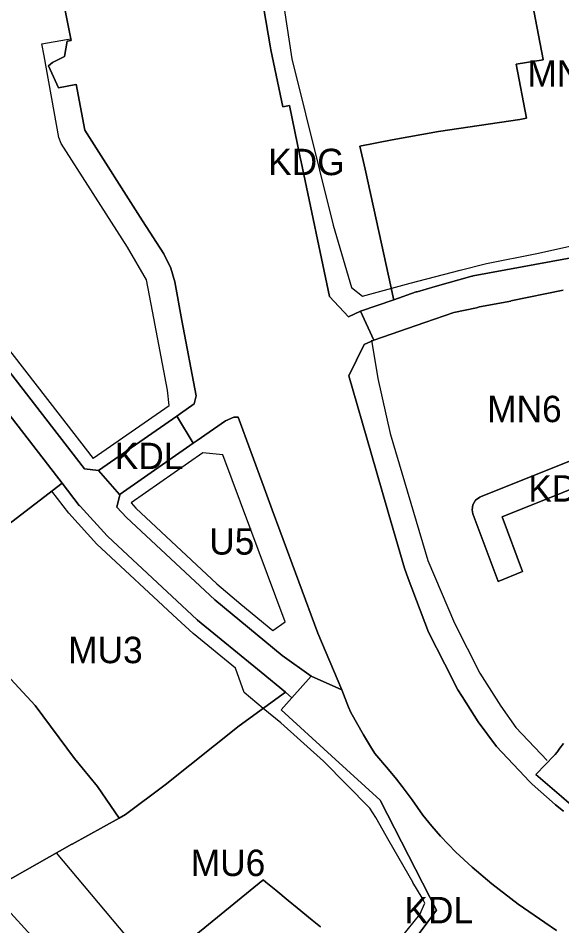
# Model space of a CAD drawing. Extents: x 7425930 to 7427318, y 5544765 to 5546387.
# Drawn here: x 7426439.3 to 7426645.2, y 5545452.3 to 5545796 of the extents above; entities that cross this region are included whole.
import ezdxf

# ---------------------------------------------------------------- set-up
doc = ezdxf.new("R2010")
doc.units = 0
for name, color, linetype in [('linie_rozgraniczajace', 7, 'Continuous'), ('linie_zabudowy_nieprzekraczalne', 7, 'Continuous'), ('linie_zabudowy_obowiazujace', 7, 'Continuous'), ('oznaczenia_przeznaczen', 7, 'Continuous')]:
    doc.layers.add(name, color=color, linetype=linetype)

msp = doc.modelspace()

# ---------------------------------------------------------------- linework, layer by layer
at = {"layer": 'linie_rozgraniczajace'}
for points in [[(7426447.87, 5545845.05), (7426459.42, 5545787.56), (7426457.84, 5545787.26), (7426456.9, 5545781.47), (7426452.3, 5545779.26), (7426450.8, 5545778.01), (7426454.62, 5545769.7), (7426461.08, 5545770.97), (7426461.28, 5545771.01), (7426464.58, 5545753.6), (7426486.44, 5545719.27), (7426494.43, 5545706.82), (7426497.07, 5545701.4), (7426498.59, 5545696.17), (7426501.33, 5545681.57), (7426506.68, 5545653), (7426505.96, 5545649.94), (7426500.78, 5545646.33), (7426499.36, 5545645.35), (7426469.76, 5545624.76), (7426469.68, 5545624.71), (7426464.41, 5545625.34), (7426433.81, 5545664.85)], [(7426532.42, 5545618.16), (7426522.61, 5545644.9), (7426520.99, 5545644.97), (7426517.82, 5545643.57), (7426507.1, 5545636.11), (7426505.62, 5545635.09), (7426499.62, 5545644.93), (7426499.36, 5545645.35), (7426500.78, 5545646.33), (7426505.96, 5545649.94), (7426506.68, 5545653), (7426501.33, 5545681.57), (7426498.59, 5545696.17), (7426497.07, 5545701.4), (7426494.43, 5545706.82), (7426486.44, 5545719.27), (7426464.58, 5545753.6), (7426461.28, 5545771.01), (7426461.08, 5545770.97), (7426454.62, 5545769.7), (7426450.8, 5545778.01), (7426452.3, 5545779.26), (7426456.9, 5545781.47), (7426457.84, 5545787.26), (7426459.42, 5545787.56), (7426447.87, 5545845.05)], [(7426633.53, 5545804.85), (7426638.17, 5545780.35), (7426638.18, 5545780.26), (7426627.94, 5545778.61), (7426631.87, 5545758.22), (7426629.33, 5545757.61), (7426598.54, 5545753.05), (7426580.92, 5545749.95), (7426568.66, 5545747.58), (7426570.69, 5545738.81), (7426575.93, 5545715.21), (7426580.59, 5545693.9), (7426581.51, 5545689.69), (7426581.57, 5545689.43), (7426568.96, 5545685.11), (7426564.43, 5545682.89), (7426564.36, 5545682.96), (7426557.22, 5545690.67), (7426546.43, 5545741.58), (7426546.1, 5545743.22), (7426542.11, 5545763), (7426539.54, 5545762.48), (7426535.03, 5545783.99), (7426534.76, 5545785.52), (7426532.31, 5545799.5)], [(7426653.57, 5545706.21), (7426611.6, 5545698.43), (7426611.35, 5545698.35), (7426611.06, 5545698.3), (7426597.17, 5545694.36), (7426590.38, 5545692.43), (7426590.17, 5545692.35), (7426590.07, 5545692.34), (7426581.57, 5545689.43), (7426581.51, 5545689.69), (7426580.59, 5545693.9), (7426575.93, 5545715.21), (7426570.69, 5545738.81), (7426568.66, 5545747.58), (7426580.92, 5545749.95), (7426598.54, 5545753.05), (7426629.33, 5545757.61), (7426631.87, 5545758.22), (7426627.94, 5545778.61), (7426638.18, 5545780.26), (7426638.17, 5545780.35), (7426633.53, 5545804.85)], [(7426532.31, 5545799.5), (7426534.76, 5545785.52), (7426535.03, 5545783.99), (7426539.54, 5545762.48), (7426542.11, 5545763), (7426546.1, 5545743.22), (7426546.43, 5545741.58), (7426557.22, 5545690.67), (7426564.36, 5545682.96), (7426564.43, 5545682.89), (7426568.96, 5545685.11), (7426573.97, 5545674.14), (7426570.32, 5545672.51), (7426564.48, 5545660.63), (7426573.02, 5545631.31), (7426579.48, 5545609), (7426584.14, 5545592.92), (7426585.64, 5545587.75), (7426586.95, 5545583.91), (7426594.73, 5545563.56), (7426600.87, 5545551.44), (7426605.82, 5545541.68), (7426607.44, 5545539.13), (7426613.55, 5545529.57), (7426620.5, 5545520.28), (7426631.12, 5545508.97), (7426632.89, 5545507.09), (7426633.81, 5545506.11), (7426633.95, 5545505.96), (7426642.73, 5545498.28), (7426642.85, 5545498.19), (7426645.86, 5545495.82)], [(7426573.97, 5545674.14), (7426568.96, 5545685.11), (7426581.57, 5545689.43), (7426590.07, 5545692.34), (7426590.17, 5545692.35), (7426590.38, 5545692.43), (7426597.17, 5545694.36), (7426611.06, 5545698.3), (7426611.35, 5545698.35), (7426611.6, 5545698.43), (7426653.57, 5545706.21), (7426690.23, 5545714.04), (7426693.12, 5545717.84), (7426693.16, 5545754.39), (7426691.09, 5545799.24)], [(7426645.86, 5545495.82), (7426642.85, 5545498.19), (7426642.73, 5545498.28), (7426633.95, 5545505.96), (7426633.81, 5545506.11), (7426632.89, 5545507.09), (7426631.12, 5545508.97), (7426620.5, 5545520.28), (7426613.55, 5545529.57), (7426607.44, 5545539.13), (7426605.82, 5545541.68), (7426600.87, 5545551.44), (7426594.73, 5545563.56), (7426586.95, 5545583.91), (7426585.64, 5545587.75), (7426584.14, 5545592.92), (7426579.48, 5545609), (7426573.02, 5545631.31), (7426564.48, 5545660.63), (7426570.32, 5545672.51), (7426573.97, 5545674.14), (7426593.36, 5545680.78), (7426604.32, 5545684.59), (7426612.88, 5545686.35), (7426614.07, 5545686.68), (7426625.85, 5545688.87), (7426625.93, 5545688.96), (7426645.7, 5545693.04)], [(7426645.7, 5545693.04), (7426625.93, 5545688.96), (7426625.85, 5545688.87), (7426614.07, 5545686.68), (7426612.88, 5545686.35), (7426604.32, 5545684.59), (7426593.36, 5545680.78), (7426573.97, 5545674.14)], [(7426433.81, 5545664.85), (7426464.41, 5545625.34), (7426469.68, 5545624.71), (7426469.76, 5545624.76), (7426477.73, 5545615.69), (7426477.83, 5545615.58), (7426476.72, 5545610.81), (7426480.26, 5545606.98), (7426513.72, 5545575.74), (7426539.25, 5545554.74), (7426539.34, 5545554.67), (7426550.3, 5545546.84), (7426542.98, 5545538.66), (7426541.77, 5545539.72), (7426540.51, 5545540.76), (7426531.27, 5545548.36), (7426507.25, 5545568.12), (7426507.16, 5545568.24), (7426507.02, 5545568.33), (7426473.3, 5545599.79), (7426473.3, 5545599.8), (7426473.04, 5545600.05), (7426462.72, 5545611.22), (7426462.66, 5545611.31), (7426462.44, 5545611.55), (7426455.9, 5545619.99), (7426425.97, 5545658.64)], [(7426689.19, 5545644.7), (7426614.38, 5545614.72), (7426614.27, 5545614.65), (7426614.14, 5545614.61), (7426612.56, 5545613.46), (7426611.54, 5545611.8), (7426611.24, 5545609.87), (7426611.55, 5545608.34), (7426620.92, 5545583.04), (7426621.07, 5545582.67), (7426621.08, 5545582.66), (7426630.29, 5545586.51), (7426622.62, 5545607.25), (7426690.87, 5545634.61)], [(7426643.25, 5545450.62), (7426638.81, 5545453.6), (7426628.68, 5545460.56), (7426618.65, 5545468.24), (7426611.24, 5545474.56), (7426605.09, 5545480.27), (7426599.21, 5545486.31), (7426596.02, 5545490.05), (7426592.6, 5545494.21), (7426588.46, 5545500.03), (7426584.74, 5545505.13), (7426582.57, 5545507.82), (7426579.54, 5545511.57), (7426574.44, 5545517.57), (7426572.74, 5545520.28), (7426570.05, 5545524.67), (7426565.25, 5545533.17), (7426564.46, 5545535.13), (7426561.84, 5545541.67), (7426552.79, 5545563.13), (7426538.37, 5545602.09), (7426535.52, 5545609.8), (7426532.42, 5545618.16)], [(7426431.69, 5545550.74), (7426445.73, 5545535.75), (7426460.58, 5545515.7), (7426469.29, 5545505.13), (7426477.5, 5545493.11), (7426459.71, 5545483.3), (7426459.74, 5545483.26), (7426459.56, 5545483.25), (7426428.57, 5545465.75), (7426450.76, 5545441.52)], [(7426579.11, 5545433.17), (7426597.8, 5545458.3), (7426576.58, 5545499.62), (7426576.41, 5545499.94), (7426557.99, 5545516.71), (7426538.9, 5545534.1), (7426542.98, 5545538.66), (7426550.3, 5545546.84), (7426561.84, 5545541.67), (7426564.46, 5545535.13), (7426565.25, 5545533.17), (7426570.05, 5545524.67), (7426572.74, 5545520.28), (7426574.44, 5545517.57), (7426579.54, 5545511.57), (7426582.57, 5545507.82), (7426584.74, 5545505.13), (7426588.46, 5545500.03), (7426592.6, 5545494.21), (7426596.02, 5545490.05), (7426599.21, 5545486.31), (7426605.09, 5545480.27), (7426611.24, 5545474.56), (7426618.65, 5545468.24), (7426628.68, 5545460.56), (7426638.81, 5545453.6), (7426643.25, 5545450.62)], [(7426450.76, 5545441.52), (7426428.57, 5545465.75), (7426459.56, 5545483.25), (7426459.74, 5545483.26), (7426459.71, 5545483.3), (7426477.5, 5545493.11), (7426479.91, 5545494.44), (7426494.94, 5545505.78), (7426523.03, 5545528.1), (7426540.51, 5545540.76), (7426541.77, 5545539.72), (7426542.98, 5545538.66), (7426538.9, 5545534.1), (7426557.99, 5545516.71), (7426576.41, 5545499.94), (7426576.58, 5545499.62), (7426597.8, 5545458.3), (7426579.11, 5545433.17)], [(7426647.96, 5545498.81), (7426645.06, 5545501.29), (7426644.16, 5545502.06), (7426635.33, 5545509.61), (7426635.37, 5545509.65), (7426635.54, 5545509.83), (7426642.33, 5545516.81), (7426642.74, 5545517.23), (7426643.32, 5545518.03), (7426643.7, 5545518.53), (7426644.51, 5545519.55), (7426645.78, 5545521.33)], [(7426645.78, 5545521.33), (7426644.51, 5545519.55), (7426643.7, 5545518.53), (7426643.32, 5545518.03), (7426642.74, 5545517.23), (7426642.33, 5545516.81), (7426635.54, 5545509.83), (7426635.37, 5545509.65), (7426635.33, 5545509.61), (7426644.16, 5545502.06), (7426645.06, 5545501.29), (7426647.96, 5545498.81)], [(7426495.6, 5545439.93), (7426531.91, 5545469.68), (7426532.09, 5545469.79), (7426533.14, 5545468.93), (7426536.89, 5545465.84), (7426541.59, 5545461.97), (7426544.95, 5545459.2), (7426550.61, 5545454.54), (7426553.81, 5545451.91)], [(7426553.81, 5545451.91), (7426550.61, 5545454.54), (7426544.95, 5545459.2), (7426541.59, 5545461.97), (7426536.89, 5545465.84), (7426533.14, 5545468.93), (7426532.09, 5545469.79), (7426531.91, 5545469.68), (7426495.6, 5545439.93)]]:
    msp.add_lwpolyline(points, dxfattribs=at)
for points in [[(7426361.44, 5545664.65), (7426388.71, 5545691.33), (7426399.82, 5545683.39), (7426405.76, 5545679.14), (7426415.34, 5545671.27), (7426425.97, 5545658.64), (7426455.9, 5545619.99), (7426407.38, 5545582.7), (7426396.9, 5545600.49), (7426392.62, 5545609.79), (7426367.86, 5545650.72), (7426367.21, 5545651.78), (7426367.21, 5545651.77)], [(7426469.76, 5545624.76), (7426499.36, 5545645.35), (7426499.62, 5545644.93), (7426505.62, 5545635.09), (7426477.88, 5545615.79), (7426477.83, 5545615.58), (7426477.73, 5545615.69)], [(7426476.72, 5545610.81), (7426477.83, 5545615.58), (7426477.88, 5545615.79), (7426505.62, 5545635.09), (7426507.1, 5545636.11), (7426517.82, 5545643.57), (7426520.99, 5545644.97), (7426522.61, 5545644.9), (7426532.42, 5545618.16), (7426535.52, 5545609.8), (7426538.37, 5545602.09), (7426552.79, 5545563.13), (7426561.84, 5545541.67), (7426550.3, 5545546.84), (7426539.34, 5545554.67), (7426539.25, 5545554.74), (7426513.72, 5545575.74), (7426480.26, 5545606.98)], [(7426611.24, 5545609.87), (7426611.54, 5545611.8), (7426612.56, 5545613.46), (7426614.14, 5545614.61), (7426614.27, 5545614.65), (7426614.38, 5545614.72), (7426689.19, 5545644.7), (7426690.9, 5545634.6), (7426690.87, 5545634.61), (7426622.62, 5545607.25), (7426630.29, 5545586.51), (7426621.08, 5545582.66), (7426621.07, 5545582.67), (7426620.92, 5545583.04), (7426611.55, 5545608.34)], [(7426407.38, 5545582.7), (7426455.9, 5545619.99), (7426462.44, 5545611.55), (7426462.66, 5545611.31), (7426462.72, 5545611.22), (7426473.04, 5545600.05), (7426473.3, 5545599.8), (7426473.3, 5545599.79), (7426507.02, 5545568.33), (7426507.16, 5545568.24), (7426507.25, 5545568.12), (7426531.27, 5545548.36), (7426540.51, 5545540.76), (7426523.03, 5545528.1), (7426494.94, 5545505.78), (7426479.91, 5545494.44), (7426477.5, 5545493.11), (7426469.29, 5545505.13), (7426460.58, 5545515.7), (7426445.73, 5545535.75), (7426431.69, 5545550.74), (7426422.04, 5545563.32), (7426413.81, 5545573.71), (7426407.56, 5545582.39)]]:
    msp.add_lwpolyline(points, close=True, dxfattribs=at)
at = {"layer": 'linie_zabudowy_nieprzekraczalne'}
for points in [[(7426569.69, 5545690.72), (7426587.81, 5545695.73), (7426606.67, 5545700.62), (7426616.7, 5545703.11), (7426635.7, 5545706.93), (7426677.92, 5545716.2), (7426689.33, 5545716.53), (7426689.12, 5545752.02), (7426688.79, 5545763.54), (7426689.21, 5545787.87), (7426687.3, 5545803.81), (7426682.63, 5545830.15), (7426680.5, 5545841.74), (7426673, 5545873.88), (7426664.59, 5545872.76), (7426637.08, 5545872.3), (7426614.1, 5545874.15), (7426585.78, 5545881.94), (7426534.93, 5545898.54), (7426528.78, 5545897.54)], [(7426443.73, 5545865.96), (7426432.22, 5545861.25), (7426395.52, 5545845.46), (7426353.35, 5545830.06), (7426347.36, 5545827.81), (7426348.63, 5545820.68), (7426351.91, 5545803.67), (7426353.32, 5545767.25), (7426353.81, 5545745.29), (7426357.55, 5545734.85), (7426361.44, 5545730.11), (7426368.02, 5545724.69), (7426377.36, 5545717.98), (7426413.08, 5545692.56), (7426426.16, 5545681.9), (7426436.87, 5545669.1), (7426455.17, 5545645.48), (7426467.74, 5545629.31)], [(7426509.26, 5545631.43), (7426482.06, 5545612.55), (7426483.86, 5545610.5), (7426514.55, 5545581.83), (7426523.6, 5545574.12), (7426535.76, 5545564.13)], [(7426532.12, 5545534.68), (7426524.93, 5545540.65), (7426521.64, 5545549.92), (7426505.52, 5545563.06), (7426499.53, 5545568.57), (7426469.13, 5545596.86), (7426458.46, 5545608.61), (7426452.03, 5545616.95)], [(7426453.7, 5545479.94), (7426490.8, 5545435.83), (7426541.62, 5545393.94), (7426554.17, 5545409.67), (7426577.53, 5545439.41), (7426591.38, 5545456.69), (7426593.37, 5545460.97)]]:
    msp.add_lwpolyline(points, dxfattribs=at)
at = {"layer": 'linie_zabudowy_obowiazujace'}
for points in [[(7426528.78, 5545897.54), (7426535.58, 5545841.02), (7426539.13, 5545805.68), (7426542.92, 5545780.68), (7426558.59, 5545717.64), (7426565.5, 5545694.09), (7426569.69, 5545690.72)], [(7426467.74, 5545629.44), (7426496.47, 5545649.3), (7426495.86, 5545655.12), (7426490.2, 5545685.14), (7426487.87, 5545696.96), (7426480.68, 5545709.31), (7426455.53, 5545748.54), (7426454.64, 5545750.88), (7426449.16, 5545781.8), (7426448.3, 5545786.31), (7426457.62, 5545787.93), (7426459.3, 5545788.25), (7426450.72, 5545830.85), (7426443.75, 5545865.97)], [(7426573.1, 5545674.14), (7426575.57, 5545659.61), (7426580.17, 5545638.73), (7426594.47, 5545590.72), (7426604.55, 5545566.98), (7426614.13, 5545547.98), (7426622.05, 5545535.46), (7426627.8, 5545527.48), (7426639.69, 5545514.98)], [(7426535.76, 5545564.13), (7426540.46, 5545567.43), (7426516.84, 5545630.68), (7426509.26, 5545631.43)], [(7426593.37, 5545460.97), (7426592.31, 5545462.88), (7426588.81, 5545468.8), (7426588.76, 5545468.88), (7426579.84, 5545484.43), (7426579.82, 5545484.45), (7426574.74, 5545493.37), (7426572.51, 5545496.89), (7426554.98, 5545514.73), (7426538.77, 5545529.16), (7426532.12, 5545534.68)]]:
    msp.add_lwpolyline(points, dxfattribs=at)

# ---------------------------------------------------------------- texts
at = {"layer": 'oznaczenia_przeznaczen'}
for s, p in [('MN3', (7426632.15, 5545770.08)), ('KDG', (7426533.98, 5545736.58)), ('MN6', (7426616.93, 5545643.05)), ('KDL', (7426475.89, 5545625.27)), ('KDD', (7426632.51, 5545612.96)), ('U5', (7426511.66, 5545592.9)), ('MU3', (7426458.22, 5545551.79)), ('MU6', (7426504.65, 5545471.19)), ('KDL', (7426585.6, 5545453.29))]:
    msp.add_text(s, height=10, dxfattribs=at).set_placement(p)

doc.saveas('drawing.dxf')
